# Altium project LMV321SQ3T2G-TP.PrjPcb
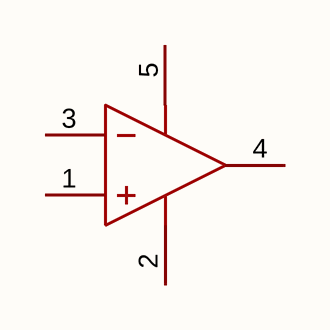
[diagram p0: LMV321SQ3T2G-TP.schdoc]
1 sheet, 1 parts. Net scope: global (net labels, ports and power ports of the same name join across sheets).

## Sheet LMV321SQ3T2G-TP.schdoc
size 127 x 101 mm

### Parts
U?  lmv321sq3t2g-tp  [SOT-353-5_L2.0-W1.6-P0.65-LS2.1-BL]  (value not drawn)

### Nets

Not connected (* = marked no-connect by the designer): U? 1(Non-inverting_input) 2(VDD) 3(Inverting_input) 4(Output) 5(VCC)

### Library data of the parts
U? = lmv321sq3t2g-tp: Manufacturer: TECH PUBLIC(台舟); AddInBom: yes; ModelId: 09e153e3f5c7488aac8a155ea9f165d5; ModelTransform: 78.74,82.677,0,0,0,0,0,0,0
